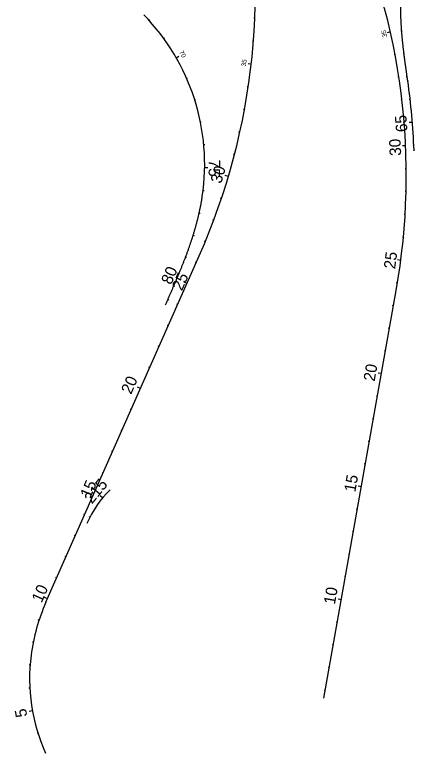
# Model space of a CAD drawing. Extents: x 448091 to 665917, y 1461380 to 1587607.
# Drawn here: x 555930 to 557668, y 1492712 to 1495926 of the extents above; entities that cross this region are included whole.
import ezdxf

# ---------------------------------------------------------------- set-up
doc = ezdxf.new("R2010")
doc.units = 0
doc.layers.add('TextShtNo', color=7, linetype='Continuous')
doc.layers.add('TextTitle', color=7, linetype='Continuous')

msp = doc.modelspace()

# ---------------------------------------------------------------- linework, layer by layer
at = {"layer": 'TextShtNo'}
for p, q in [((556065.4, 1493369.3), (556732, 1494876.5)), ((557275, 1492951.3), (557589.1, 1494726.6))]:
    msp.add_line(p, q, dxfattribs=at)
for centre, radius, start, end in [((554112.2, 1496035.2), 2864.7, 336.1403, 12.1472), ((554768.3, 1495225.8), 2864.7, 349.9658, 24.4399), ((555821.8, 1495274.1), 934.2, 351.4736, 44.2633), ((554768.3, 1495225.8), 2900.7, 2.1837, 8.1837), ((556680.2, 1493519.6), 477.5, 134.6787, 156.1403), ((556835.6, 1493028.7), 842.1, 156.1403, 172.4803), ((556779.3, 1493036.1), 785.4, 172.4803, 204.3515)]:
    msp.add_arc(centre, radius, start, end, dxfattribs=at)
for points in [[(557639.4, 1495638.7), (557638.7, 1495643.7), (557638, 1495648.7), (557637.2, 1495653.7), (557636.5, 1495658.7), (557635.8, 1495663.7), (557635.1, 1495668.7), (557634.4, 1495673.8), (557633.7, 1495678.8), (557633, 1495683.8), (557632.3, 1495688.8), (557631.5, 1495693.8), (557630.9, 1495698.9), (557630.2, 1495703.9), (557629.5, 1495708.9), (557628.8, 1495713.9), (557628.1, 1495718.9), (557627.4, 1495724), (557626.8, 1495729), (557626.1, 1495734), (557625.5, 1495739), (557624.8, 1495744.1), (557624.2, 1495749.1), (557623.5, 1495754.1), (557622.9, 1495759.1), (557622.3, 1495764.2), (557621.7, 1495769.2), (557621.1, 1495774.2), (557620.5, 1495779.3), (557619.9, 1495784.3), (557619.4, 1495789.3), (557618.8, 1495794.4), (557618.3, 1495799.4), (557617.8, 1495804.5), (557617.2, 1495809.5), (557616.7, 1495814.5), (557616.2, 1495819.6), (557615.8, 1495824.6), (557615.3, 1495829.7), (557614.8, 1495834.7), (557614.4, 1495839.8), (557614, 1495844.8), (557613.6, 1495849.9), (557613.2, 1495854.9), (557612.8, 1495860), (557612.4, 1495865), (557612.1, 1495870.1), (557611.7, 1495875.1), (557611.4, 1495880.2), (557611.1, 1495885.3), (557610.9, 1495890.3), (557610.6, 1495895.4), (557610.4, 1495900.4), (557610.1, 1495905.5), (557609.9, 1495910.6), (557609.7, 1495915.6), (557609.6, 1495920.7), (557609.4, 1495925.8), (557609.3, 1495930.8), (557609.2, 1495935.9), (557609.1, 1495941), (557609.1, 1495946), (557609, 1495951.1), (557609, 1495956.2), (557609, 1495961.2), (557609.1, 1495966.3), (557609.1, 1495971.4), (557609.2, 1495976.4), (557609.3, 1495981.5), (557609.4, 1495986.6), (557609.6, 1495991.6), (557609.8, 1495996.7), (557610, 1496001.8), (557610.2, 1496006.8), (557610.5, 1496011.9)], [(556585.4, 1494663.7), (556588.2, 1494669.8), (556590.9, 1494676), (556593.6, 1494682.2), (556596.4, 1494688.4), (556599.1, 1494694.6), (556601.8, 1494700.7), (556604.5, 1494706.9), (556607.2, 1494713.1), (556610, 1494719.3), (556612.7, 1494725.5), (556615.4, 1494731.7), (556618.1, 1494737.9), (556620.7, 1494744.1), (556623.4, 1494750.3), (556626.1, 1494756.5), (556628.7, 1494762.7), (556631.4, 1494768.9), (556634, 1494775.1), (556636.7, 1494781.4), (556639.3, 1494787.6), (556641.9, 1494793.8), (556644.5, 1494800.1), (556647.1, 1494806.3), (556649.6, 1494812.6), (556652.2, 1494818.8), (556654.7, 1494825.1), (556657.2, 1494831.4), (556659.7, 1494837.6), (556662.2, 1494843.9), (556664.7, 1494850.2), (556667.1, 1494856.5), (556669.6, 1494862.8), (556672, 1494869.1), (556674.4, 1494875.4), (556676.7, 1494881.8), (556679.1, 1494888.1), (556681.4, 1494894.4), (556683.7, 1494900.8), (556686, 1494907.2), (556688.2, 1494913.5), (556690.5, 1494919.9), (556692.7, 1494926.3), (556694.9, 1494932.7), (556697, 1494939.1), (556699.1, 1494945.5), (556701.2, 1494951.9), (556703.3, 1494958.4), (556705.3, 1494964.8), (556707.3, 1494971.3), (556709.3, 1494977.7), (556711.3, 1494984.2), (556713.2, 1494990.7), (556715, 1494997.2), (556716.9, 1495003.7), (556718.7, 1495010.2), (556720.5, 1495016.7), (556722.2, 1495023.2), (556723.9, 1495029.8), (556725.6, 1495036.3), (556727.2, 1495042.9), (556728.8, 1495049.4), (556730.4, 1495056), (556731.9, 1495062.6), (556733.3, 1495069.2), (556734.8, 1495075.8), (556736.2, 1495082.4), (556737.5, 1495089), (556738.8, 1495095.7), (556740.1, 1495102.3), (556741.3, 1495108.9), (556742.4, 1495115.6), (556743.6, 1495122.3), (556744.6, 1495128.9), (556745.7, 1495135.6)]]:
    msp.add_spline(points, degree=3, dxfattribs=at)
at = {"layer": 'TextTitle'}
for p, q in [((556974.2, 1495910.9), (556970.2, 1495911.1)), ((556514.5, 1495900.9), (556517.4, 1495903.6)), ((557563.8, 1495851.2), (557550.2, 1495848.2)), ((557613.2, 1495855), (557609.2, 1495854.7)), ((556577.5, 1495823.3), (556580.7, 1495825.7)), ((556968.1, 1495811.1), (556964.1, 1495811.4)), ((556631.8, 1495739.4), (556644, 1495746.4)), ((557584, 1495753.3), (557580, 1495752.5)), ((557623.4, 1495755.6), (557619.4, 1495755.1)), ((556958.5, 1495711.6), (556944.6, 1495713.2)), ((556676.9, 1495650.2), (556680.6, 1495651.9)), ((557600.7, 1495654.7), (557596.7, 1495654.1)), ((557636.8, 1495656.5), (557632.9, 1495655.9)), ((556945.5, 1495612.5), (556941.5, 1495613)), ((556712.2, 1495556.7), (556716, 1495557.9)), ((557613.9, 1495555.6), (557609.9, 1495555.1)), ((557649.9, 1495557.3), (557646, 1495556.9)), ((556929, 1495513.8), (556925.1, 1495514.6)), ((556737.3, 1495460), (556741.2, 1495460.8)), ((557623.7, 1495456), (557619.7, 1495455.7)), ((557659.6, 1495457.8), (557645.7, 1495456.7)), ((556909.1, 1495415.8), (556905.2, 1495416.7)), ((556751.9, 1495361.1), (556755.9, 1495361.5)), ((557665.9, 1495358), (557661.9, 1495357.8)), ((557630, 1495356.3), (557616, 1495355.6)), ((556885.8, 1495318.6), (556881.9, 1495319.6)), ((556755.9, 1495261.2), (556769.9, 1495261)), ((557632.8, 1495256.3), (557628.8, 1495256.3)), ((556859.1, 1495222.2), (556845.7, 1495226.2)), ((556749.2, 1495161.5), (556753.1, 1495161)), ((557632.1, 1495156.3), (557628.1, 1495156.4)), ((556829, 1495126.9), (556825.2, 1495128.1)), ((556732, 1495063), (556735.9, 1495062.2)), ((557627.9, 1495056.4), (557623.9, 1495056.6)), ((556795.7, 1495032.6), (556791.9, 1495034)), ((556705.9, 1494966.5), (556709.7, 1494965.3)), ((556759, 1494939.5), (556755.3, 1494941.1)), ((557620.3, 1494956.7), (557616.3, 1494957.1)), ((556673.1, 1494872.1), (556676.8, 1494870.6)), ((556719.3, 1494847.8), (556715.7, 1494849.4)), ((557609.2, 1494857.3), (557595.3, 1494859.1)), ((556635.8, 1494779.3), (556648.7, 1494773.8)), ((556678.9, 1494756.3), (556666.1, 1494762)), ((557594.6, 1494758.4), (557590.6, 1494759)), ((556596, 1494687.6), (556599.7, 1494685.9)), ((556638.4, 1494664.9), (556634.8, 1494666.5)), ((557577.3, 1494659.9), (557573.4, 1494660.6)), ((556598, 1494573.4), (556594.3, 1494575)), ((557559.9, 1494561.4), (557556, 1494562.1)), ((556557.5, 1494482), (556553.9, 1494483.6)), ((557542.5, 1494463), (557538.5, 1494463.6)), ((556517.1, 1494390.5), (556513.4, 1494392.1)), ((557525, 1494364.5), (557511.3, 1494366.9)), ((556476.6, 1494299), (556463.8, 1494304.7)), ((557507.6, 1494266), (557503.7, 1494266.7)), ((556436.2, 1494207.6), (556432.5, 1494209.2)), ((557490.2, 1494167.5), (557486.3, 1494168.2)), ((556395.7, 1494116.1), (556392.1, 1494117.8)), ((557472.8, 1494069.1), (557468.8, 1494069.8)), ((556355.3, 1494024.7), (556351.6, 1494026.3)), ((557455.3, 1493970.6), (557451.4, 1493971.3)), ((556314.8, 1493933.2), (556311.2, 1493934.8)), ((557437.9, 1493872.1), (557424.1, 1493874.6)), ((556274.4, 1493841.8), (556270.7, 1493843.4)), ((556311.9, 1493823.4), (556301.1, 1493832.3)), ((556233.9, 1493750.3), (556230.3, 1493751.9)), ((557420.5, 1493773.7), (557416.6, 1493774.4)), ((556256.8, 1493740.2), (556253.2, 1493742)), ((556193.5, 1493658.9), (556189.8, 1493660.5)), ((557403.1, 1493675.2), (557399.1, 1493675.9)), ((556153, 1493567.4), (556149.4, 1493569)), ((557385.7, 1493576.7), (557381.7, 1493577.4)), ((556112.6, 1493476), (556108.9, 1493477.6)), ((557368.2, 1493478.2), (557364.3, 1493478.9)), ((556072.1, 1493384.5), (556059.3, 1493390.2)), ((557350.8, 1493379.8), (557337, 1493382.2)), ((556035.5, 1493291.5), (556031.7, 1493292.8)), ((557333.4, 1493281.3), (557329.4, 1493282)), ((556010, 1493194.9), (556006.1, 1493195.7)), ((557316, 1493182.8), (557312, 1493183.5)), ((555996.2, 1493095.9), (555992.2, 1493096.2)), ((557298.5, 1493084.4), (557294.6, 1493085.1)), ((555995, 1492996), (555991, 1492995.8)), ((557281.1, 1492985.9), (557277.2, 1492986.6)), ((556006.4, 1492896.7), (555992.6, 1492894.2)), ((556030.4, 1492799.7), (556026.6, 1492798.5))]:
    msp.add_line(p, q, dxfattribs=at)
for centre in [(557639.4, 1495638.6), (557666.8, 1495336.3)]:
    msp.add_circle(centre, 0.8, dxfattribs=at)

# ---------------------------------------------------------------- texts
for s, height, rotation, p in [('35', 20, 102.6115, (557550.3, 1495830.5)), ('70', 20, 299.8757, (556644, 1495763.6)), ('35', 20, 83.5136, (556935.2, 1495700.7)), ('65', 50, 94.5888, (557638.6, 1495417.7)), ('30', 50, 92.611, (557611.1, 1495313.2)), ('75', 50, 269.2091, (556773.8, 1495296)), ('30', 50, 73.5132, (556827.5, 1495188.6)), ('25', 50, 82.6105, (557584.4, 1494817.7)), ('80', 50, 67.1159, (556610.1, 1494748.4)), ('25', 50, 66.1403, (556656.9, 1494721.5)), ('20', 50, 79.9654, (557495.2, 1494328.3)), ('20', 50, 66.1403, (556435.7, 1494271.5)), ('15', 50, 79.9654, (557411.2, 1493846.4)), ('15', 50, 66.1403, (556257.4, 1493818.3)), ('215', 50, 50.4839, (556265.9, 1493794.8)), ('10', 50, 66.1403, (556046.4, 1493363.8)), ('10', 50, 79.9654, (557322.4, 1493357.5)), ('5', 50, 100.2229, (555984.5, 1492873.1))]:
    msp.add_text(s, height=height, rotation=rotation, dxfattribs=at).set_placement(p)

doc.saveas('drawing.dxf')
